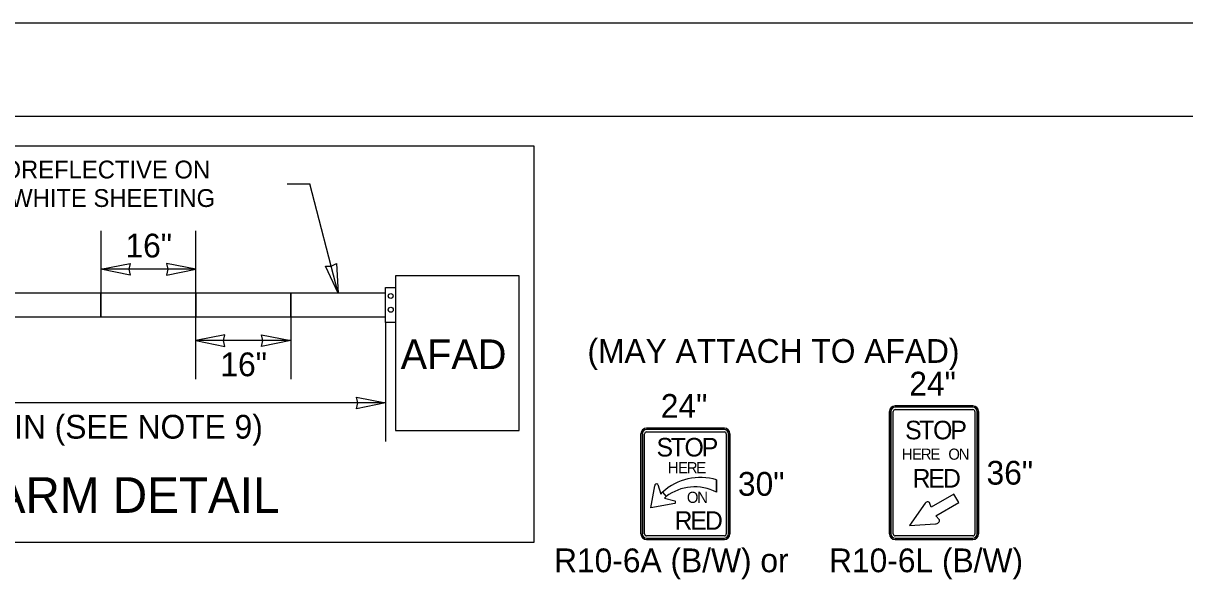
# Model space of a CAD drawing. Extents: x 99999.1 to 100095.7, y 99995 to 100010.7.
# Drawn here: x 100049.243 to 100053.158, y 100008.807 to 100010.687 of the extents above; entities that cross this region are included whole.
import ezdxf

# ---------------------------------------------------------------- set-up
doc = ezdxf.new("R2010")
doc.units = 0
for name, color, linetype in [('SH_GI_PlotLimits', 7, 'Continuous'), ('SH_GI_SheetBorder', 7, 'Continuous'), ('TR_SN_ConstructionSigns', 7, 'Continuous'), ('TR_WZ_WorkZoneDetails', 7, 'Continuous')]:
    doc.layers.add(name, color=color, linetype=linetype)

msp = doc.modelspace()

# ---------------------------------------------------------------- linework, layer by layer
at = {"layer": 'SH_GI_PlotLimits'}
msp.add_lwpolyline([(100039.0625, 99999.6875), (100056.0625, 99999.6875), (100056.0625, 100010.6875), (100039.0625, 100010.6875)], close=True, dxfattribs=at)
at = {"layer": 'SH_GI_SheetBorder'}
msp.add_line((100040, 100010.375), (100055.75, 100010.375), dxfattribs=at)
at = {"layer": 'TR_SN_ConstructionSigns'}
for p, q in [((100052.4441, 100009.3991), (100052.1816, 100009.3991)), ((100052.1816, 100009.3991), (100052.4441, 100009.3991)), ((100052.4441, 100009.3991), (100052.1816, 100009.3991)), ((100052.4441, 100009.3944), (100052.1816, 100009.3944)), ((100052.1629, 100009.3804), (100052.1629, 100008.9679)), ((100052.1629, 100008.9679), (100052.1629, 100009.3804)), ((100052.1629, 100009.3804), (100052.1629, 100008.9679)), ((100052.1676, 100009.3804), (100052.1676, 100008.9679)), ((100052.1754, 100008.9679), (100052.1754, 100009.3804)), ((100052.1816, 100009.3866), (100052.4441, 100009.3866)), ((100052.4504, 100009.3804), (100052.4504, 100008.9679)), ((100052.4582, 100008.9679), (100052.4582, 100009.3804)), ((100052.4629, 100008.9679), (100052.4629, 100009.3804)), ((100052.4629, 100009.3804), (100052.4629, 100008.9679)), ((100052.4629, 100008.9679), (100052.4629, 100009.3804)), ((100051.6061, 100009.3241), (100051.3436, 100009.3241)), ((100051.3436, 100009.3241), (100051.6061, 100009.3241)), ((100051.6061, 100009.3241), (100051.3436, 100009.3241)), ((100051.3436, 100009.3241), (100051.6061, 100009.3241)), ((100051.6061, 100009.3194), (100051.3436, 100009.3194)), ((100051.3249, 100009.3054), (100051.3249, 100008.9679)), ((100051.3249, 100008.9679), (100051.3249, 100009.3054)), ((100051.3249, 100009.3054), (100051.3249, 100008.9679)), ((100051.3249, 100008.9679), (100051.3249, 100009.3054)), ((100051.3296, 100009.3054), (100051.3296, 100008.9679)), ((100051.3374, 100008.9679), (100051.3374, 100009.3054)), ((100051.3436, 100009.3116), (100051.6061, 100009.3116)), ((100051.6124, 100009.3054), (100051.6124, 100008.9679)), ((100051.6202, 100008.9679), (100051.6202, 100009.3054)), ((100051.6249, 100008.9679), (100051.6249, 100009.3054)), ((100051.6249, 100009.3054), (100051.6249, 100008.9679)), ((100051.6249, 100008.9679), (100051.6249, 100009.3054)), ((100051.6249, 100009.3054), (100051.6249, 100008.9679)), ((100051.3577, 100009.0554), (100051.3713, 100009.1298)), ((100051.3821, 100009.1346), (100051.3915, 100009.1022)), ((100051.5798, 100009.1503), (100051.5795, 100009.1084)), ((100051.5795, 100009.1084), (100051.5798, 100009.1503)), ((100051.3915, 100009.1022), (100051.3979, 100009.1086)), ((100051.3979, 100009.1086), (100051.4095, 100009.0937)), ((100051.3979, 100009.1086), (100051.4095, 100009.0937)), ((100051.4095, 100009.0937), (100051.4048, 100009.0889)), ((100051.4048, 100009.0889), (100051.439, 100009.0797)), ((100052.3796, 100009.1022), (100052.303, 100009.058)), ((100052.396, 100009.0738), (100052.3796, 100009.1022)), ((100051.4388, 100009.0704), (100051.3577, 100009.0554)), ((100052.2824, 100009.0718), (100052.2298, 100008.9961)), ((100052.303, 100009.058), (100052.2992, 100009.0706)), ((100052.3186, 100009.0291), (100052.396, 100009.0738)), ((100052.3309, 100009.0154), (100052.3186, 100009.0291)), ((100052.2298, 100008.9961), (100052.3176, 100009.0022)), ((100051.6061, 100008.9616), (100051.3436, 100008.9616)), ((100051.3436, 100008.9538), (100051.6061, 100008.9538)), ((100051.3436, 100008.9491), (100051.6061, 100008.9491)), ((100051.6061, 100008.9491), (100051.3436, 100008.9491)), ((100051.3436, 100008.9491), (100051.6061, 100008.9491)), ((100051.6061, 100008.9491), (100051.3436, 100008.9491)), ((100052.4441, 100008.9616), (100052.1816, 100008.9616)), ((100052.1816, 100008.9538), (100052.4441, 100008.9538)), ((100052.1816, 100008.9491), (100052.4441, 100008.9491)), ((100052.4441, 100008.9491), (100052.1816, 100008.9491)), ((100052.1816, 100008.9491), (100052.4441, 100008.9491))]:
    msp.add_line(p, q, dxfattribs=at)
for centre, radius, start, end in [((100052.1816, 100009.3804), 0.0187, 90, 180), ((100052.1816, 100009.3804), 0.0187, 90, 180), ((100052.1816, 100009.3804), 0.0187, 90, 180), ((100052.1816, 100009.3804), 0.0141, 90, 180), ((100052.4441, 100009.3804), 0.0187, 0, 90), ((100052.4441, 100009.3804), 0.0187, 0, 90), ((100052.4441, 100009.3804), 0.0187, 0, 90), ((100052.4441, 100009.3804), 0.0141, 0, 90), ((100052.1816, 100009.3804), 0.00625, 90, 180), ((100052.4441, 100009.3804), 0.00625, 0, 90), ((100051.3436, 100009.3054), 0.0187, 90, 180), ((100051.3436, 100009.3054), 0.0187, 90, 180), ((100051.3436, 100009.3054), 0.0187, 90, 180), ((100051.3436, 100009.3054), 0.0187, 90, 180), ((100051.3436, 100009.3054), 0.0141, 90, 180), ((100051.6061, 100009.3054), 0.0187, 0, 90), ((100051.6061, 100009.3054), 0.0187, 0, 90), ((100051.6061, 100009.3054), 0.0187, 0, 90), ((100051.6061, 100009.3054), 0.0187, 0, 90), ((100051.6061, 100009.3054), 0.0141, 0, 90), ((100051.3436, 100009.3054), 0.00625, 90, 180), ((100051.6061, 100009.3054), 0.00625, 0, 90), ((100051.5261, 100008.9672), 0.1909, 73.6434, 132.2131), ((100051.5261, 100008.9672), 0.1909, 73.6434, 132.2131), ((100051.506, 100008.9678), 0.1586, 62.4149, 127.4769), ((100051.506, 100008.9678), 0.1586, 62.4149, 127.4769), ((100051.3436, 100008.9679), 0.0187, 180, 270), ((100051.3436, 100008.9679), 0.0187, 180, 270), ((100051.3436, 100008.9679), 0.0187, 180, 270), ((100051.3436, 100008.9679), 0.0187, 180, 270), ((100051.3436, 100008.9679), 0.0141, 180, 270), ((100051.3436, 100008.9679), 0.00625, 180, 270), ((100051.6061, 100008.9679), 0.0187, 270, 0), ((100051.6061, 100008.9679), 0.0187, 270, 0), ((100051.6061, 100008.9679), 0.0187, 270, 0), ((100051.6061, 100008.9679), 0.0141, 270, 0), ((100051.6061, 100008.9679), 0.00625, 270, 0), ((100051.6061, 100008.9679), 0.0187, 270, 0), ((100052.1816, 100008.9679), 0.0187, 180, 270), ((100052.1816, 100008.9679), 0.0187, 180, 270), ((100052.1816, 100008.9679), 0.0187, 180, 270), ((100052.1816, 100008.9679), 0.0141, 180, 270), ((100052.1816, 100008.9679), 0.00625, 180, 270), ((100052.4441, 100008.9679), 0.0187, 270, 0), ((100052.4441, 100008.9679), 0.0187, 270, 0), ((100052.4441, 100008.9679), 0.0187, 270, 0), ((100052.4441, 100008.9679), 0.0141, 270, 0), ((100052.4441, 100008.9679), 0.00625, 270, 0)]:
    msp.add_arc(centre, radius, start, end, dxfattribs=at)
for centre, major_axis, ratio, start_param, end_param in [((100051.3777, 100009.1299), (-0.00647, -0.00009), 0.989437, 3.962549, 6.283185), ((100051.4366, 100009.0751), (-0.0046, 0.00239), 0.999053, 2.490568, 4.712389), ((100052.2891, 100009.0675), (0.00934, 0.00539), 0.700347, 5.977036, 8.198856), ((100052.3216, 100009.0104), (-0.00913, -0.00527), 0.700347, 0.771965, 3.092601)]:
    msp.add_ellipse(centre, major_axis=major_axis, ratio=ratio, start_param=start_param, end_param=end_param, dxfattribs=at)
at = {"layer": 'TR_WZ_WorkZoneDetails'}
for p, q in [((100050.1326, 100010.147), (100050.2088, 100010.147)), ((100050.3043, 100009.779), (100050.2088, 100010.147)), ((100049.5043, 100009.989), (100049.5043, 100009.779)), ((100049.8243, 100009.779), (100049.8243, 100009.989)), ((100049.8243, 100009.859), (100049.5043, 100009.859)), ((100049.8243, 100009.489), (100049.8243, 100009.699)), ((100050.1443, 100009.699), (100050.1443, 100009.489)), ((100050.4643, 100009.6797), (100050.4643, 100009.279)), ((100050.1443, 100009.619), (100049.8243, 100009.619)), ((100050.4643, 100009.409), (100048.6643, 100009.409))]:
    msp.add_line(p, q, dxfattribs=at)
for points in [[(100047.6374, 100010.275), (100050.9639, 100010.275), (100050.9639, 100008.939), (100047.6374, 100008.939)], [(100049.5043, 100009.859), (100049.6026, 100009.8783), (100049.5981, 100009.859), (100049.6026, 100009.8397)], [(100049.8243, 100009.859), (100049.7261, 100009.8783), (100049.7306, 100009.859), (100049.7261, 100009.8397)], [(100050.3043, 100009.779), (100050.2611, 100009.8693), (100050.2809, 100009.8697), (100050.2984, 100009.879)], [(100050.4643, 100009.7983), (100050.4977, 100009.7983), (100050.4977, 100009.6797), (100050.4643, 100009.6797)], [(100049.8243, 100009.619), (100049.9226, 100009.5997), (100049.9181, 100009.619), (100049.9226, 100009.6383)], [(100050.1443, 100009.619), (100050.0461, 100009.5997), (100050.0506, 100009.619), (100050.0461, 100009.6383)], [(100050.4643, 100009.409), (100050.3661, 100009.3897), (100050.3706, 100009.409), (100050.3661, 100009.4283)]]:
    msp.add_lwpolyline(points, close=True, dxfattribs=at)
for points in [[(100050.4977, 100009.6797), (100050.4977, 100009.3163), (100050.9139, 100009.3163), (100050.9139, 100009.8374), (100050.4977, 100009.8374), (100050.4977, 100009.7983), (100050.4977, 100009.6797)], [(100050.9139, 100009.8374), (100050.4977, 100009.8374), (100050.4977, 100009.3163), (100050.9139, 100009.3163), (100050.9139, 100009.8374)], [(100050.4643, 100009.779), (100048.6643, 100009.779), (100048.6643, 100009.699), (100050.4643, 100009.699), (100050.4643, 100009.779)], [(100049.1843, 100009.699), (100049.5043, 100009.699), (100049.5043, 100009.779), (100049.1843, 100009.779), (100049.1843, 100009.699)], [(100049.5043, 100009.699), (100049.8243, 100009.699), (100049.8243, 100009.779), (100049.5043, 100009.779), (100049.5043, 100009.699)], [(100049.8243, 100009.699), (100050.1443, 100009.699), (100050.1443, 100009.779), (100049.8243, 100009.779), (100049.8243, 100009.699)], [(100050.1443, 100009.699), (100050.4643, 100009.699), (100050.4643, 100009.779), (100050.1443, 100009.779), (100050.1443, 100009.699)]]:
    msp.add_lwpolyline(points, dxfattribs=at)
for centre, radius in [((100050.4813, 100009.7693), 0.00828), ((100050.4813, 100009.7229), 0.00855)]:
    msp.add_circle(centre, radius, dxfattribs=at)

# ---------------------------------------------------------------- texts
at = {"layer": 'TR_SN_ConstructionSigns'}
for s, p in [('(MAY ATTACH TO AFAD)', (100051.1446, 100009.5441)), ('24"', (100052.2295, 100009.4341)), ('24"', (100051.3918, 100009.3591)), ('36"', (100052.4898, 100009.1341)), ('30"', (100051.6518, 100009.0966)), ('R10-6A (B/W) or', (100051.032, 100008.8391)), ('R10-6L (B/W)', (100051.959, 100008.8391))]:
    msp.add_text(s, height=0.08, rotation=360, dxfattribs=at).set_placement(p)
for s, height, p in [('S', 0.0625, (100052.2154, 100009.2866)), ('T', 0.0625, (100052.2629, 100009.2866)), ('O', 0.0625, (100052.3097, 100009.2866)), ('P', 0.0625, (100052.3679, 100009.2866)), ('S', 0.0625, (100051.3774, 100009.2288)), ('T', 0.0625, (100051.4249, 100009.2288)), ('O', 0.0625, (100051.4717, 100009.2288)), ('P', 0.0625, (100051.5299, 100009.2288)), ('H', 0.0375, (100052.2043, 100009.2179)), ('E', 0.0375, (100052.2388, 100009.2179)), ('R', 0.0375, (100052.2684, 100009.2179)), ('E', 0.0375, (100052.3003, 100009.2179)), ('O', 0.0375, (100052.3611, 100009.2179)), ('N', 0.0375, (100052.3959, 100009.2179)), ('H', 0.0375, (100051.4152, 100009.1726)), ('E', 0.0375, (100051.4497, 100009.1726)), ('R', 0.0375, (100051.4794, 100009.1726)), ('E', 0.0375, (100051.5112, 100009.1726)), ('R', 0.0625, (100052.2404, 100009.1241)), ('E', 0.0625, (100052.2935, 100009.1241)), ('D', 0.0625, (100052.3429, 100009.1241)), ('O', 0.0375, (100051.4797, 100009.0726)), ('N', 0.0375, (100051.5146, 100009.0726)), ('R', 0.0625, (100051.4381, 100008.9819)), ('E', 0.0625, (100051.4913, 100008.9819)), ('D', 0.0625, (100051.5406, 100008.9819))]:
    msp.add_text(s, height=height, dxfattribs=at).set_placement(p)
at = {"layer": 'TR_WZ_WorkZoneDetails'}
for s, height, p in [('GATE ARM SHALL BE FULLY RETROREFLECTIVE ON', 0.06, (100047.8352, 100010.165)), ('BOTH SIDES WITH ALTERNATING RED/WHITE SHEETING', 0.06, (100047.6874, 100010.069)), ('16"', 0.08, (100049.5873, 100009.899)), ('AFAD', 0.1, (100050.5149, 100009.5231)), ('16"', 0.08, (100049.9073, 100009.499)), ('78" MIN (SEE NOTE 9)', 0.08, (100048.9363, 100009.289))]:
    msp.add_text(s, height=height, dxfattribs=at).set_placement(p)
msp.add_text('AFAD GATE ARM DETAIL', height=0.12, rotation=360, dxfattribs=at).set_placement((100048.1893, 100009.039))

doc.saveas('drawing.dxf')
